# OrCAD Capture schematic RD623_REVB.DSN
size Custom
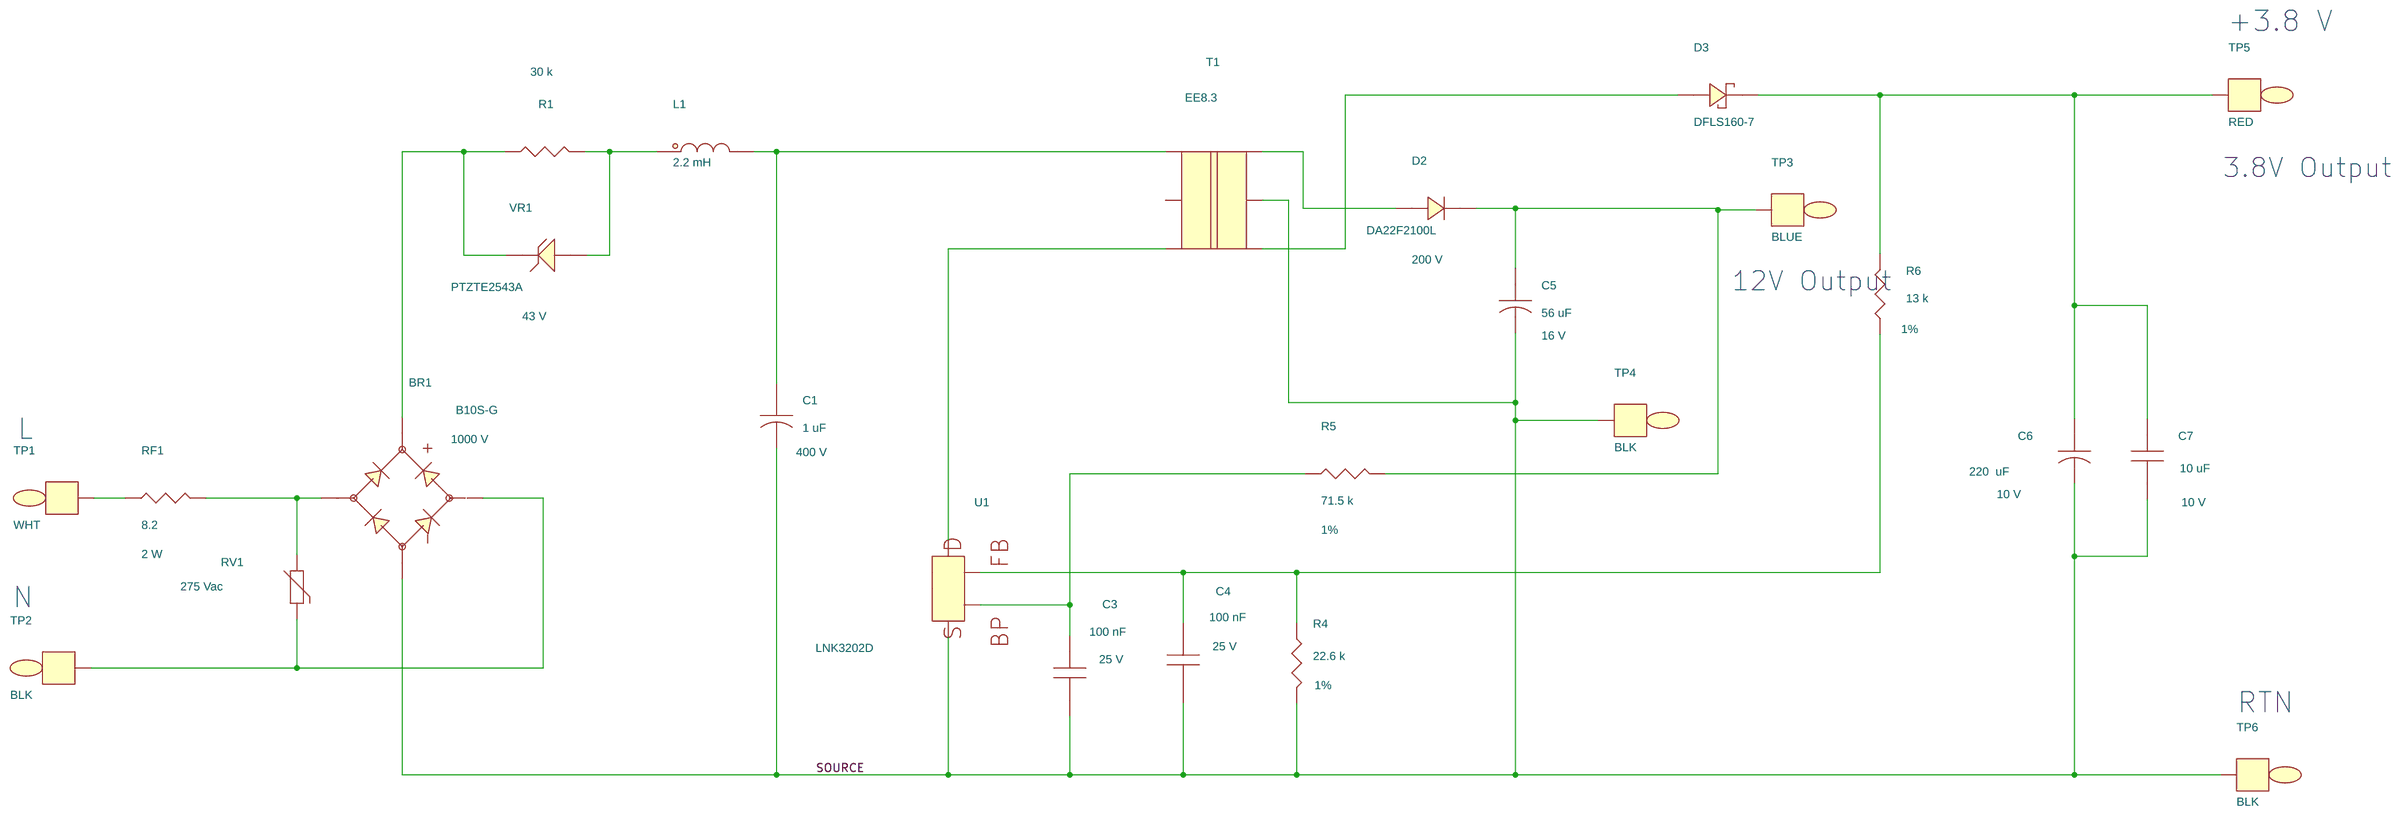
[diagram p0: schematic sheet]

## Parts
BR1  B10S-G  [pismsoic4]
C1  1 uF  [pipolcapcyld250ls100030]
C3  100 nF  [pismc0805]
C4  100 nF  [pismc0805]
C5  56 uF  [pipolcapclyd200ls80030]
C6  220  uF  [pipolcapcyld250ls100030]
C7  10 uF  [pismc0805]
D2  DA22F2100L  [pi_sm_sod-123_12]
D3  DFLS160-7  [pismddflr120012]
L1  2.2 mH  [pi_choke_RL5480-1_d2]
R1  30 k  [pismr1206]
R4  22.6 k  [pismr0603]
R5  71.5 k  [pismr1206]
R6  13 k  [pi14wresd100ls500d030]
RF1  8.2  [pi2wresd200ls725d040]
RV1  275 Vac  [pidisc350x160ls210x140040]
T1  EE8.3  [pi_bobbin_ee8_3_v6p]
TP1  WHT  [pitpkeystone100x100]
TP2  BLK  [pitpkeystone100x100]
TP3  BLUE  [pitpkeystone100x100]
TP4  BLK  [pitpkeystone100x100]
TP5  RED  [pitpkeystone100x100]
TP6  BLK  [pitpkeystone100x100]
U1  LNK3202D  [pismso8dnshort5678]
VR1  PTZTE2543A  [pismdo214ac12]

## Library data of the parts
BR1 = DIODE_BRIDGE_~~+-: ALT_SYMBOLS: pi_sm_soic4_slot; Disp_Voltage: 1000 V; FPLIST: pismsoic4,pi_sm_soic4_slot; Part Number: 15-00818-00
C1 = CAP_POL: ALT_SYMBOLS: pipolcapcyld250ls100030h; Disp_Voltage: 400 V; FPLIST: pipolcapcyld250ls100030,pipolcapcyld250ls100030h; Part Number: 20-00800-00; Voltage: 400 V
C3 C4 = CAP_NP: Disp_Voltage: 25 V; Part Number: 20-08599-00; Voltage: 25 V
C5 = CAP_POL: Disp_Voltage: 16 V; Part Number: 20-00877-00; Voltage: 16 V
C6 = CAP_POL: ALT_SYMBOLS: pipolcapcyld250ls100030h; Disp_Voltage: 10 V; FPLIST: pipolcapcyld250ls100030,pipolcapcyld250ls100030h; Part Number: 20-00002-00; Voltage: 10 V
C7 = CAP_NP: Disp_Voltage: 10 V; Part Number: 20-01021-00; Voltage: 10 V
D2 = DIODE: Disp_Voltage: 200 V; Part Number: 15-01018-00
D3 = DIODE_SCHOTTKY: Part Number: 15-00880-00
L1 = INDUCTOR_dot2: Part Number: 30-00272-00
R1 = R: Part Number: 05-01387-00
R4 = R: Disp_Tol: 1%; Part Number: 05-03218-00; Tol: 1%
R5 = R: Disp_Tol: 1%; Part Number: 05-00371-00
R6 = R: ALT_SYMBOLS: pi14wvresd100ls200d030,pi14wresd100ls400d030,pi14wresd100ls500d030; Disp_Tol: 1%; FPLIST: pi14wvresd100ls100d030,pi14wvresd100ls200d030,pi14wresd100ls400d030,pi14wresd100ls500d030; Part Number: 05-02083-00
RF1 = RF: ALT_SYMBOLS: pi2wresd200ls900d040,pi2wvresd200ls300d040,pi2wvresd200ls400d040,pi2wvresd180ls250d040,pi2wvresd180ls200d040; Disp_Power: 2 W; FPLIST: pi2wresd200ls725d040,pi2wresd200ls900d040,pi2wvresd200ls300d040,pi2wvresd200ls400d040,pi2wvresd180ls250d040,pi2wvresd180ls200d040; Part Number: 05-03076-00
RV1 = VARISTOR: ALT_SYMBOLS: pi_disc_354x220_ls220x10_040_h; FPLIST: pidisc350x160ls210x140040,pi_disc_354x220_ls220x10_040_h; Part Number: 85-00015-00
T1 = BEE8_3_6P: Part Number: 25-01086-00
TP1 = TESTPOINT: Part Number: 35-00081-00
TP2 TP4 TP6 = TESTPOINT: Part Number: 35-00079-00
TP3 = TESTPOINT: Part Number: 35-00397-00
TP5 = TESTPOINT: Part Number: 35-00080-00
U1 = LNK32XX_8C: Part Number: 10-00949-00
VR1 = DIODE_ZENER: Disp_Voltage: 43 V; Part Number: 15-01238-00

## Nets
SOURCE: BR1.4 C1.2 C3.2 C4.2 C5.2 C6.2 C7.2 R4.2 T1.5 TP4.1 TP6.1 U1.5(S) U1.6(SOURCE) U1.7(SOURCE) U1.8(SOURCE)
N25701: C1.1 L1.1 T1.1
N25747: T1.3 U1.4(D)
N25978: C4.1 R4.1 R6.1 U1.2(FB)
N46358: D3.2 T1.4
N138558: C3.1 R5.1 U1.1(BP)
N149717: L1.2 R1.1 VR1.2
N156669: BR1.2 RV1.2 TP2.1
N156684: BR1.1 RF1.2 RV1.1
N157774: D2.2 T1.6
N157829: C5.1 D2.1 R5.2 TP3.1
N159322: C6.1 C7.1 D3.1 R6.2 TP5.1
N165873: BR1.3 R1.2 VR1.1
N172947: RF1.1 TP1.1

Not connected (* = marked no-connect by the designer): T1 2

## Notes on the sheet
- +3.8 V
- 3.8V Output
- 12V Output
- L
- N
- RTN
